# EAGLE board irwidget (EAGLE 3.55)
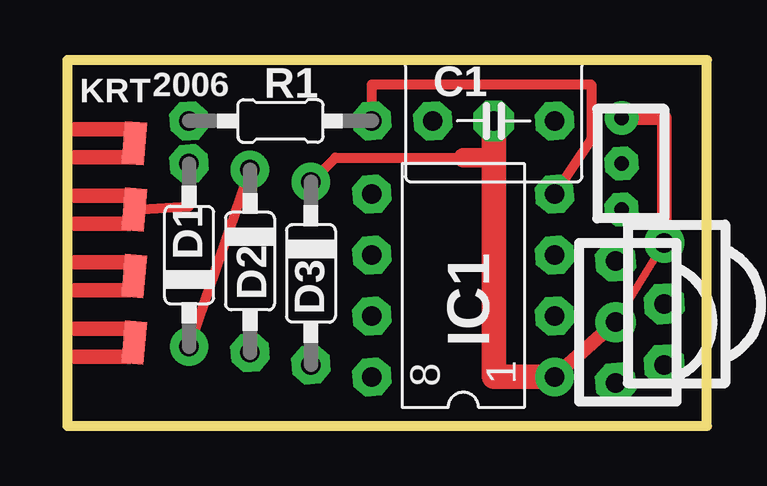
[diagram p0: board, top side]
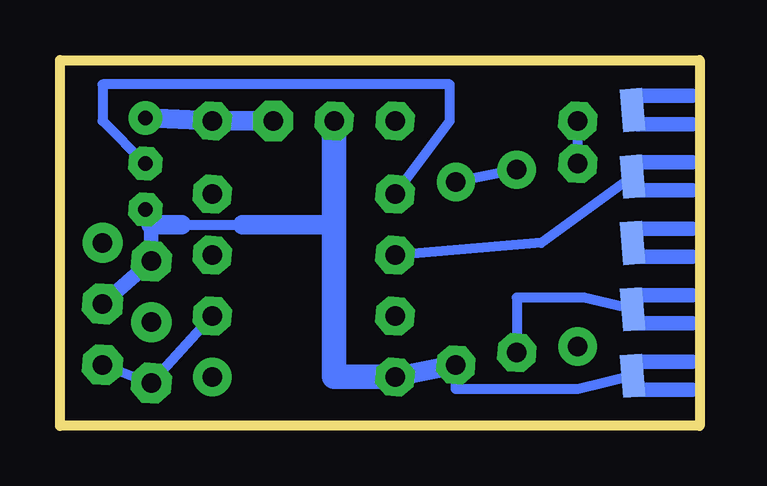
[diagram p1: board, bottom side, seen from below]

Size 26.67 x 15.24 mm. Coordinates in mm from the lower left corner, seen from the top.
Outline: 0,0 26.67,0 26.67,15.24 0,15.24 0,0
Copper layers used: Top, Bottom

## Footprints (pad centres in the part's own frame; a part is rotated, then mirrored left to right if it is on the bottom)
B5 = drill 0.813 pad 1.6 octagon:  -2.54,0;  2.54,0
0 = drill 0.813 pad 1.6 octagon:  -5.08,0 | drill 0.813 pad 1.6 round:  2.54,0
L8 = drill 0.813 pad 1.6 round:  -3.81,-3.81 | drill 0.813 pad 1.6 octagon:  -1.27,-3.81;  1.27,-3.81;  3.81,-3.81;  3.81,3.81;  1.27,3.81;  -1.27,3.81;  -3.81,3.81
9PCBEG = smd 0.914 x 1.778 rotated 4.5:  -2.794,0 | smd 0.914 x 1.778 rotated 4.4:  -2.794,2.769 | smd 0.914 x 1.778 rotated 4.3:  -2.794,5.537 | smd 0.914 x 1.778 rotated 4.6:  -2.794,-2.769 | smd 0.914 x 1.778 rotated 4.7:  -2.794,-5.537 | smd 0.914 x 1.778 rotated 4.9 bottom:  -2.794,-1.384 | smd 0.914 x 1.778 rotated 4.8 bottom:  -2.794,1.384 | smd 0.914 x 1.778 rotated 4.7 bottom:  -2.794,4.153 | smd 0.914 x 1.778 rotated 5 bottom:  -2.794,-4.153
DET = drill 0.61 pad 1.397 round:  0,1.905 | drill 0.61 pad 1.397 octagon:  0,0;  0,-1.905
30 = drill 0.813 pad 1.6 octagon:  -5.08,0;  2.54,0
DM-OPG = drill 0.813 pad 1.676 round:  0,0 | drill 0.813 pad 1.676 octagon:  0,2.54;  0,-2.54
DM-OGP = drill 0.813 pad 1.676 octagon:  0,0;  0,-2.54 | drill 0.813 pad 1.676 round:  0,2.54

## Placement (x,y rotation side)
C1  2.2 uF  [B5]  17.78,12.7 0 top
D1  1N4148  [0]  7.62,8.13 90 top
D2  1N4148  [0]  5.08,5.84 270 top
D3  1N5231  [0]  10.16,7.62 90 top
IC1  12F629  [L8]  16.51,5.84 90 top
J1  DE9F  [9PCBEG]  0,7.62 0 bottom
M1  QSE15X  [DET]  23.11,10.92 0 top
R1  10k  [30]  10.16,12.7 0 top
U$2  IRDM-OPG  [DM-OPG]  22.86,4.32 0 top
U$3  IRDM-OGP  [DM-OGP]  24.89,5.08 0 top

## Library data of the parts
C1 = cap
D1-D3 = my_diode
IC1 = pic
J1 = my_conn
M1 U$2 U$3 = my_ir_mo
R1 = myresist

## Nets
J1: D1. J1.
N$1: C1. D1. D2. D3. IC1. M1. U$2. U$3.
N$2: IC1. M1.
N$3: IC1. U$2. U$3.
N$11: C1. D3. IC1. J1. M1. U$2. U$3.
N$14: IC1. J1.
N$19: D2. J1. R1.
N$21: IC1. R1.

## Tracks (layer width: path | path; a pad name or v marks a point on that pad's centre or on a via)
J1
  Bottom 0.406: 2.79,4.85 4.83,5.33 7.62,5.33 7.62,3.05
N$1  (via drill 0.81 pad 1.68)
  Top 0.305: 24.89,7.62 22.86,4.32
  Top 0.406: D2. D1. | 16.51,11.18 11.18,11.18 D3.
  Top 0.61: 24.89,7.62 24.89,12.83 23.11,12.83 | 20.32,2.03 22.86,4.32
  Top 0.813: 16.51,11.18 17.78,11.18
  Top 1.016: v17.78,12.7 17.78,11.18 17.78,2.03 20.32,2.03
  Bottom 0.406: D1. D3.
  Bottom 0.813: 23.11,12.83 C1. v17.78,12.7
N$2
  Bottom 0.406: 12.7,9.65 10.41,12.7 10.41,14.22 24.89,14.22 24.89,12.7 23.11,10.92
N$3
  Bottom 0.406: 20.32,4.57 U$2. U$3.
N$11
  Bottom 0.406: 10.16,2.54 10.16,1.52 5.08,1.52 2.79,2.08 | 21.59,8.38 19.05,8.38
  Bottom 0.61: M1. 22.86,8.38 22.86,6.86 24.89,5.08
  Bottom 0.813: 10.16,2.54 IC1. | 22.86,8.38 21.59,8.38 | 19.05,8.38 15.24,8.38
  Bottom 1.016: IC1. 15.24,2.03 15.24,8.38 15.24,12.7
N$14
  Bottom 0.406: 2.79,10.39 6.6,7.62 12.7,7.11
N$19
  Top 0.406: 2.79,9 5.08,9.14 5.08,10.92
  Bottom 0.406: 5.08,10.92 5.08,12.7
N$21
  Top 0.406: R1. 12.7,14.22 21.84,14.22 21.84,11.94 20.32,9.65

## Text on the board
tPlace: 2006 | KRT
_layer121: 2006 | KRT | 8 | 1
_layer125: R1 | C1 | D2 | D1 | D3 | IC1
